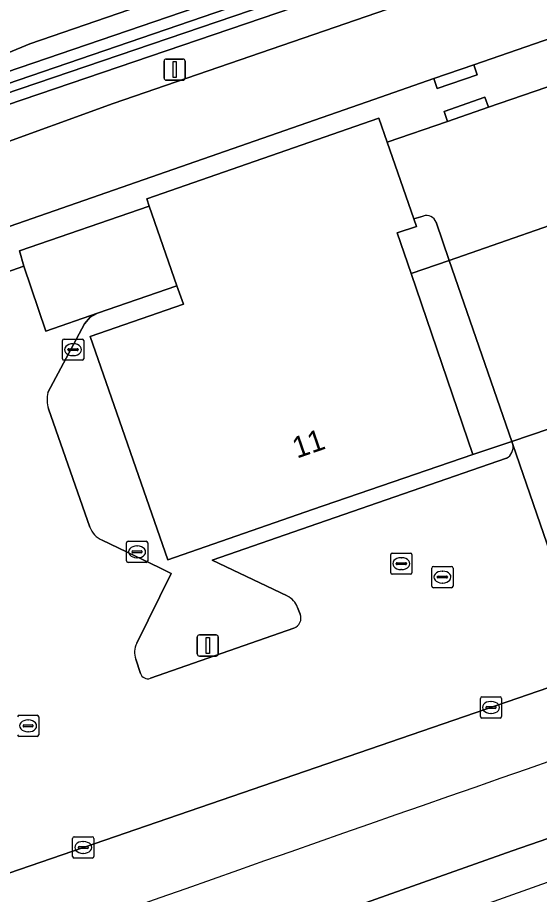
# Model space of a CAD drawing. Extents: x 162722 to 165104, y 384719 to 386284.
# Drawn here: x 164345.99 to 164370.59, y 385035.99 to 385077.31 of the extents above; entities that cross this region are included whole.
import ezdxf

# ---------------------------------------------------------------- set-up
doc = ezdxf.new("R2010")
doc.units = 0
for name, color, linetype in [('IMGEO_Fietspad_gesloten', 7, 'Continuous'), ('IMGEO_Groenvoorziening', 7, 'Continuous'), ('IMGEO_Kolk', 7, 'Continuous'), ('IMGEO_Lichtmast', 7, 'Continuous'), ('IMGEO_Loofbos', 7, 'Continuous'), ('IMGEO_Oever', 7, 'Continuous'), ('IMGEO_Pand', 7, 'Continuous'), ('IMGEO_Pand_nummerreeks', 7, 'Continuous'), ('IMGEO_Rijbaan_lokaal_gesloten', 7, 'Continuous'), ('IMGEO_Rijbaan_lokaal_open', 7, 'Continuous'), ('IMGEO_Rijbaan_regionaal_gesloten', 7, 'Continuous'), ('IMGEO_Voetpad_open', 7, 'Continuous'), ('IMGEO_Waterloop', 7, 'Continuous')]:
    doc.layers.add(name, color=color, linetype=linetype)

msp = doc.modelspace()

# ---------------------------------------------------------------- linework, layer by layer
at = {"layer": 'IMGEO_Fietspad_gesloten'}
for points in [[(164466.181, 385089.048), (164427.545, 385091.818), (164418.054, 385092.109), (164412.215, 385091.866), (164406.354, 385091.275), (164400.57, 385090.162), (164394.908, 385088.537), (164394.768, 385088.49), (164350.497, 385073.252), (164344.679, 385071.162), (164339.92, 385069.199), (164335.356, 385066.818), (164331.022, 385064.04), (164330.205, 385063.452), (164324.126, 385058.927), (164318.998, 385054.383), (164302.831, 385039.299), (164298.74, 385035.835), (164287.625, 385027.549), (164277.433, 385021.678), (164264.35, 385015.493), (164257.963, 385012.93)], [(164327.55, 385057.035), (164334.25, 385061.89), (164338.691, 385064.518), (164343.864, 385066.861), (164362.775, 385073.454), (164365.605, 385074.433), (164367.49, 385075.085), (164373.207, 385077.063), (164384.303, 385080.902), (164395.855, 385084.899), (164397.125, 385085.361), (164401.283, 385086.604), (164405.535, 385087.47), (164409.848, 385087.953), (164416.397, 385088.485), (164423.747, 385088.458), (164461.35, 385085.769)]]:
    msp.add_lwpolyline(points, dxfattribs=at)
at = {"layer": 'IMGEO_Groenvoorziening'}
for points in [[(164318.998, 385054.383), (164324.126, 385058.927), (164330.205, 385063.452), (164331.022, 385064.04), (164335.356, 385066.818), (164339.92, 385069.199), (164344.679, 385071.162), (164350.497, 385073.252), (164394.768, 385088.49), (164394.908, 385088.537), (164400.57, 385090.162), (164406.354, 385091.275), (164412.215, 385091.866), (164418.054, 385092.109), (164427.545, 385091.818), (164466.181, 385089.048)], [(164394.261, 385089.79), (164343.975, 385072.685)], [(164338.19, 385071.882), (164343.523, 385074.069), (164369.019, 385082.793), (164369.388, 385083.93), (164346.566, 385076.077), (164337.165, 385072.178), (164331.331, 385068.992), (164325.863, 385065.214), (164323.916, 385063.651), (164304.537, 385046.531), (164287.51, 385032.763), (164285.664, 385031.439), (164282.177, 385029.02), (164268.08, 385024.03), (164269.878, 385021.502), (164272.892, 385022.978)], [(164403.278, 385056.814), (164393.631, 385053.501), (164373.041, 385046.43), (164335.102, 385033.4), (164334.393, 385033.02), (164328.747, 385028.379)]]:
    msp.add_lwpolyline(points, dxfattribs=at)
msp.add_arc((165538.698, 381680.665), 3558.615, 108.517916, 109.869036, dxfattribs=at)
at = {"layer": 'IMGEO_Kolk'}
for p, q in [((164348.104, 385061.236), (164348.104, 385062.088)), ((164348.179, 385062.162), (164349.031, 385062.162)), ((164349.105, 385062.088), (164349.105, 385061.236)), ((164348.363, 385061.656), (164348.363, 385061.668)), ((164348.406, 385061.705), (164348.804, 385061.705)), ((164348.592, 385061.942), (164348.617, 385061.942)), ((164348.847, 385061.668), (164348.847, 385061.656)), ((164348.801, 385061.619), (164348.403, 385061.619)), ((164348.615, 385061.382), (164348.59, 385061.382)), ((164349.031, 385061.162), (164348.179, 385061.162)), ((164351.122, 385051.71), (164351.122, 385052.562)), ((164351.197, 385052.636), (164352.049, 385052.636)), ((164352.123, 385052.562), (164352.123, 385051.71)), ((164351.381, 385052.13), (164351.381, 385052.142)), ((164351.424, 385052.179), (164351.822, 385052.179)), ((164351.61, 385052.416), (164351.635, 385052.416)), ((164351.865, 385052.142), (164351.865, 385052.13)), ((164351.819, 385052.093), (164351.421, 385052.093)), ((164351.633, 385051.856), (164351.608, 385051.856)), ((164363.573, 385051.154), (164363.573, 385052.006)), ((164363.648, 385052.08), (164364.5, 385052.08)), ((164364.061, 385051.86), (164364.086, 385051.86)), ((164364.574, 385052.006), (164364.574, 385051.154)), ((164352.049, 385051.636), (164351.197, 385051.636)), ((164363.832, 385051.574), (164363.832, 385051.586)), ((164364.27, 385051.537), (164363.872, 385051.537)), ((164363.875, 385051.623), (164364.273, 385051.623)), ((164364.084, 385051.3), (164364.059, 385051.3)), ((164364.316, 385051.586), (164364.316, 385051.574)), ((164365.512, 385050.521), (164365.512, 385051.373)), ((164365.587, 385051.447), (164366.439, 385051.447)), ((164366.513, 385051.373), (164366.513, 385050.521)), ((164364.5, 385051.08), (164363.648, 385051.08)), ((164365.771, 385050.941), (164365.771, 385050.953)), ((164366.209, 385050.904), (164365.811, 385050.904)), ((164365.814, 385050.99), (164366.212, 385050.99)), ((164366, 385051.227), (164366.025, 385051.227)), ((164366.255, 385050.953), (164366.255, 385050.941)), ((164366.023, 385050.667), (164365.998, 385050.667)), ((164366.439, 385050.447), (164365.587, 385050.447)), ((164367.801, 385044.378), (164367.801, 385045.23)), ((164367.876, 385045.304), (164368.728, 385045.304)), ((164368.802, 385045.23), (164368.802, 385044.378)), ((164368.06, 385044.798), (164368.06, 385044.81)), ((164368.498, 385044.761), (164368.1, 385044.761)), ((164368.103, 385044.847), (164368.501, 385044.847)), ((164368.289, 385045.084), (164368.314, 385045.084)), ((164368.544, 385044.81), (164368.544, 385044.798)), ((164346.061, 385044.438), (164346.913, 385044.438)), ((164346.987, 385044.364), (164346.987, 385043.512)), ((164368.728, 385044.304), (164367.876, 385044.304)), ((164368.312, 385044.524), (164368.287, 385044.524)), ((164346.245, 385043.932), (164346.245, 385043.944)), ((164346.683, 385043.895), (164346.285, 385043.895)), ((164346.288, 385043.981), (164346.686, 385043.981)), ((164346.474, 385044.218), (164346.499, 385044.218)), ((164346.729, 385043.944), (164346.729, 385043.932)), ((164346.497, 385043.658), (164346.472, 385043.658)), ((164346.913, 385043.438), (164346.061, 385043.438)), ((164348.583, 385037.782), (164348.583, 385038.634)), ((164348.658, 385038.708), (164349.51, 385038.708)), ((164349.071, 385038.488), (164349.096, 385038.488)), ((164349.584, 385038.634), (164349.584, 385037.782)), ((164348.842, 385038.202), (164348.842, 385038.214)), ((164349.28, 385038.165), (164348.882, 385038.165)), ((164348.885, 385038.251), (164349.283, 385038.251)), ((164349.326, 385038.214), (164349.326, 385038.202)), ((164349.51, 385037.708), (164348.658, 385037.708)), ((164349.094, 385037.928), (164349.069, 385037.928))]:
    msp.add_line(p, q, dxfattribs=at)
for points in [[(164348.104, 385061.236), (164348.104, 385062.088)], [(164348.179, 385062.162), (164349.031, 385062.162)], [(164349.105, 385062.088), (164349.105, 385061.236)], [(164349.031, 385061.162), (164348.179, 385061.162)], [(164351.122, 385051.71), (164351.122, 385052.562)], [(164351.197, 385052.636), (164352.049, 385052.636)], [(164352.123, 385052.562), (164352.123, 385051.71)], [(164363.573, 385051.154), (164363.573, 385052.006)], [(164363.648, 385052.08), (164364.5, 385052.08)], [(164364.574, 385052.006), (164364.574, 385051.154)], [(164352.049, 385051.636), (164351.197, 385051.636)], [(164365.512, 385050.521), (164365.512, 385051.373)], [(164365.587, 385051.447), (164366.439, 385051.447)], [(164366.513, 385051.373), (164366.513, 385050.521)], [(164364.5, 385051.08), (164363.648, 385051.08)], [(164366.439, 385050.447), (164365.587, 385050.447)], [(164367.801, 385044.378), (164367.801, 385045.23)], [(164367.876, 385045.304), (164368.728, 385045.304)], [(164368.802, 385045.23), (164368.802, 385044.378)], [(164346.061, 385044.438), (164346.913, 385044.438)], [(164346.987, 385044.364), (164346.987, 385043.512)], [(164368.728, 385044.304), (164367.876, 385044.304)], [(164346.913, 385043.438), (164346.061, 385043.438)], [(164348.583, 385037.782), (164348.583, 385038.634)], [(164348.658, 385038.708), (164349.51, 385038.708)], [(164349.584, 385038.634), (164349.584, 385037.782)], [(164349.51, 385037.708), (164348.658, 385037.708)]]:
    msp.add_lwpolyline(points, dxfattribs=at)
for centre, radius, start, end in [((164348.181, 385062.086), 0.0765, 91.552, 178.448), ((164348.181, 385062.086), 0.0765, 91.552, 178.448), ((164349.029, 385062.086), 0.0765, 1.552, 88.448), ((164349.029, 385062.086), 0.0765, 1.552, 88.448), ((164348.403, 385061.665), 0.0403, 85.8775, 175.7526), ((164348.4, 385061.655), 0.0366, 178.938, 274.7102), ((164348.804, 385061.662), 0.043, 264.8664, 352.4533), ((164348.808, 385061.667), 0.0386, 1.7309, 96.639), ((164348.181, 385061.238), 0.0765, 181.552, 268.448), ((164348.181, 385061.238), 0.0765, 181.552, 268.448), ((164349.029, 385061.238), 0.0765, 271.552, 358.448), ((164349.029, 385061.238), 0.0765, 271.552, 358.448), ((164351.199, 385052.56), 0.0765, 91.552, 178.448), ((164351.199, 385052.56), 0.0765, 91.552, 178.448), ((164352.047, 385052.56), 0.0765, 1.552, 88.448), ((164352.047, 385052.56), 0.0765, 1.552, 88.448), ((164351.421, 385052.139), 0.0403, 85.8775, 175.7526), ((164351.418, 385052.129), 0.0366, 178.938, 274.7102), ((164351.822, 385052.136), 0.043, 264.8664, 352.4533), ((164351.826, 385052.141), 0.0386, 1.7309, 96.639), ((164351.199, 385051.712), 0.0765, 181.552, 268.448), ((164351.199, 385051.712), 0.0765, 181.552, 268.448), ((164352.047, 385051.712), 0.0765, 271.552, 358.448), ((164352.047, 385051.712), 0.0765, 271.552, 358.448), ((164363.65, 385052.004), 0.0765, 91.552, 178.448), ((164363.65, 385052.004), 0.0765, 91.552, 178.448), ((164364.498, 385052.004), 0.0765, 1.552, 88.448), ((164364.498, 385052.004), 0.0765, 1.552, 88.448), ((164363.872, 385051.583), 0.0403, 85.8775, 175.7526), ((164363.869, 385051.573), 0.0366, 178.938, 274.7102), ((164364.273, 385051.58), 0.043, 264.8664, 352.4533), ((164364.277, 385051.585), 0.0386, 1.7309, 96.639), ((164365.589, 385051.371), 0.0765, 91.552, 178.448), ((164365.589, 385051.371), 0.0765, 91.552, 178.448), ((164366.437, 385051.371), 0.0765, 1.552, 88.448), ((164366.437, 385051.371), 0.0765, 1.552, 88.448), ((164363.65, 385051.156), 0.0765, 181.552, 268.448), ((164363.65, 385051.156), 0.0765, 181.552, 268.448), ((164364.498, 385051.156), 0.0765, 271.552, 358.448), ((164364.498, 385051.156), 0.0765, 271.552, 358.448), ((164365.811, 385050.95), 0.0403, 85.8775, 175.7526), ((164365.808, 385050.94), 0.0366, 178.938, 274.7102), ((164366.212, 385050.947), 0.043, 264.8664, 352.4533), ((164366.216, 385050.952), 0.0386, 1.7309, 96.639), ((164365.589, 385050.523), 0.0765, 181.552, 268.448), ((164365.589, 385050.523), 0.0765, 181.552, 268.448), ((164366.437, 385050.523), 0.0765, 271.552, 358.448), ((164366.437, 385050.523), 0.0765, 271.552, 358.448), ((164367.878, 385045.228), 0.0765, 91.552, 178.448), ((164367.878, 385045.228), 0.0765, 91.552, 178.448), ((164368.726, 385045.228), 0.0765, 1.552, 88.448), ((164368.726, 385045.228), 0.0765, 1.552, 88.448), ((164368.1, 385044.807), 0.0403, 85.8775, 175.7526), ((164368.097, 385044.797), 0.0366, 178.938, 274.7102), ((164368.501, 385044.804), 0.043, 264.8664, 352.4533), ((164368.505, 385044.809), 0.0386, 1.7309, 96.639), ((164346.063, 385044.362), 0.0765, 91.552, 178.448), ((164346.063, 385044.362), 0.0765, 91.552, 178.448), ((164346.911, 385044.362), 0.0765, 1.552, 88.448), ((164346.911, 385044.362), 0.0765, 1.552, 88.448), ((164367.878, 385044.38), 0.0765, 181.552, 268.448), ((164367.878, 385044.38), 0.0765, 181.552, 268.448), ((164368.726, 385044.38), 0.0765, 271.552, 358.448), ((164368.726, 385044.38), 0.0765, 271.552, 358.448), ((164346.285, 385043.941), 0.0403, 85.8775, 175.7526), ((164346.282, 385043.931), 0.0366, 178.938, 274.7102), ((164346.686, 385043.938), 0.043, 264.8664, 352.4533), ((164346.69, 385043.943), 0.0386, 1.7309, 96.639), ((164346.063, 385043.514), 0.0765, 181.552, 268.448), ((164346.063, 385043.514), 0.0765, 181.552, 268.448), ((164346.911, 385043.514), 0.0765, 271.552, 358.448), ((164346.911, 385043.514), 0.0765, 271.552, 358.448), ((164348.66, 385038.632), 0.0765, 91.552, 178.448), ((164348.66, 385038.632), 0.0765, 91.552, 178.448), ((164349.508, 385038.632), 0.0765, 1.552, 88.448), ((164349.508, 385038.632), 0.0765, 1.552, 88.448), ((164348.882, 385038.211), 0.0403, 85.8775, 175.7526), ((164348.879, 385038.201), 0.0366, 178.938, 274.7102), ((164349.283, 385038.208), 0.043, 264.8664, 352.4533), ((164349.287, 385038.213), 0.0386, 1.7309, 96.639), ((164348.66, 385037.784), 0.0765, 181.552, 268.448), ((164348.66, 385037.784), 0.0765, 181.552, 268.448), ((164349.508, 385037.784), 0.0765, 271.552, 358.448), ((164349.508, 385037.784), 0.0765, 271.552, 358.448)]:
    msp.add_arc(centre, radius, start, end, dxfattribs=at)
for centre, major_axis, ratio, start_param, end_param in [((164348.591, 385061.662), (-0.387, 0.002), 0.722429, 4.712389, 7.853982), ((164348.616, 385061.662), (-0.39, 0.002), 0.717154, 1.570796, 4.712389), ((164351.609, 385052.136), (-0.387, 0.002), 0.722429, 4.712389, 7.853982), ((164351.634, 385052.136), (-0.39, 0.002), 0.717154, 1.570796, 4.712389), ((164364.06, 385051.58), (-0.387, 0.002), 0.722429, 4.712389, 7.853982), ((164364.085, 385051.58), (-0.39, 0.002), 0.717154, 1.570796, 4.712389), ((164365.999, 385050.947), (-0.387, 0.002), 0.722429, 4.712389, 7.853982), ((164366.024, 385050.947), (-0.39, 0.002), 0.717154, 1.570796, 4.712389), ((164368.288, 385044.804), (-0.387, 0.002), 0.722429, 4.712389, 7.853982), ((164368.313, 385044.804), (-0.39, 0.002), 0.717154, 1.570796, 4.712389), ((164346.473, 385043.938), (-0.387, 0.002), 0.722429, 4.712389, 7.853982), ((164346.498, 385043.938), (-0.39, 0.002), 0.717154, 1.570796, 4.712389), ((164349.07, 385038.208), (-0.387, 0.002), 0.722429, 4.712389, 7.853982), ((164349.095, 385038.208), (-0.39, 0.002), 0.717154, 1.570796, 4.712389)]:
    msp.add_ellipse(centre, major_axis=major_axis, ratio=ratio, start_param=start_param, end_param=end_param, dxfattribs=at)
at = {"layer": 'IMGEO_Lichtmast'}
for p, q in [((164352.996, 385075.356), (164353.786, 385075.356)), ((164353.786, 385075.356), (164352.996, 385075.356)), ((164352.896, 385074.456), (164352.896, 385075.256)), ((164352.896, 385075.256), (164352.896, 385074.456)), ((164353.886, 385075.256), (164353.886, 385074.456)), ((164353.886, 385074.456), (164353.886, 385075.256)), ((164353.786, 385074.356), (164352.996, 385074.356)), ((164352.996, 385074.356), (164353.786, 385074.356)), ((164354.458, 385047.325), (164354.458, 385048.125)), ((164354.458, 385048.125), (164354.458, 385047.325)), ((164354.558, 385048.225), (164355.348, 385048.225)), ((164355.348, 385048.225), (164354.558, 385048.225)), ((164355.448, 385048.125), (164355.448, 385047.325)), ((164355.448, 385047.325), (164355.448, 385048.125)), ((164355.348, 385047.225), (164354.558, 385047.225)), ((164354.558, 385047.225), (164355.348, 385047.225))]:
    msp.add_line(p, q, dxfattribs=at)
for points in [[(164353.316, 385075.231), (164353.466, 385075.231), (164353.466, 385074.481), (164353.316, 385074.481), (164353.316, 385075.231)], [(164354.878, 385048.1), (164355.028, 385048.1), (164355.028, 385047.35), (164354.878, 385047.35), (164354.878, 385048.1)]]:
    msp.add_lwpolyline(points, dxfattribs=at)
for centre, start, end in [((164352.996, 385075.256), 90, 180), ((164352.996, 385075.256), 90, 180), ((164353.786, 385075.256), 0, 90), ((164353.786, 385075.256), 360, 90), ((164352.996, 385074.456), 180, 270), ((164352.996, 385074.456), 180, 270), ((164353.786, 385074.456), 270, 0), ((164353.786, 385074.456), 270, 0), ((164354.558, 385048.125), 90, 180), ((164354.558, 385048.125), 90, 180), ((164355.348, 385048.125), 0, 90), ((164355.348, 385048.125), 360, 90), ((164354.558, 385047.325), 180, 270), ((164354.558, 385047.325), 180, 270), ((164355.348, 385047.325), 270, 0), ((164355.348, 385047.325), 270, 0)]:
    msp.add_arc(centre, 0.1, start, end, dxfattribs=at)
at = {"layer": 'IMGEO_Loofbos'}
msp.add_lwpolyline([(164323.916, 385063.651), (164325.863, 385065.214), (164331.331, 385068.992), (164337.165, 385072.178), (164346.566, 385076.077), (164369.388, 385083.93), (164370.132, 385086.222), (164354.56, 385083.887), (164342.433, 385082.528), (164311.293, 385079.851), (164305.339, 385078.79), (164303.964, 385078.112), (164304.036, 385077.108), (164304.185, 385074.376), (164240.8, 385051.931), (164241.35, 385051.172), (164248.33, 385041.532), (164255.248, 385033.867), (164265.342, 385027.017), (164268.08, 385024.03), (164282.177, 385029.02), (164285.664, 385031.439), (164287.51, 385032.763), (164304.537, 385046.531)], close=True, dxfattribs=at)
at = {"layer": 'IMGEO_Oever'}
for points in [[(164343.706, 385073.581), (164369.188, 385082.3), (164383.961, 385087.354), (164386.52, 385088.309), (164389.158, 385089.121), (164395.04, 385091.144), (164401.37, 385092.632), (164407.636, 385093.811), (164413.442, 385094.456), (164419.281, 385094.734), (164425.127, 385094.644), (164435.141, 385093.917), (164435.786, 385095.13), (164441.042, 385105.013)], [(164450.162, 385092.196), (164450.045, 385092.195), (164426.184, 385093.996), (164419.117, 385093.995), (164412.049, 385093.792), (164405.988, 385093.041), (164400, 385091.871), (164394.109, 385090.289), (164343.785, 385073.171)], [(164343.975, 385072.685), (164394.261, 385089.79)], [(164388.999, 385089.374), (164386.525, 385088.649), (164383.803, 385087.851), (164369.019, 385082.793), (164343.523, 385074.069), (164338.19, 385071.882)]]:
    msp.add_lwpolyline(points, dxfattribs=at)
at = {"layer": 'IMGEO_Pand'}
msp.add_lwpolyline([(164352.193, 385068.424), (164353.499, 385064.675), (164353.801, 385063.807), (164349.408, 385062.278), (164353.069, 385051.759), (164359.895, 385054.135), (164367.443, 385056.72), (164364.534, 385065.243), (164363.879, 385067.161), (164364.784, 385067.457), (164364.658, 385067.822), (164363.407, 385071.433), (164363.012, 385072.572), (164352.074, 385068.765)], close=True, dxfattribs=at)
at = {"layer": 'IMGEO_Rijbaan_lokaal_gesloten'}
msp.add_lwpolyline([(164352.193, 385068.424), (164346.073, 385066.315), (164346.281, 385065.59), (164347.323, 385062.535), (164349.748, 385063.375), (164353.499, 385064.675)], close=True, dxfattribs=at)
at = {"layer": 'IMGEO_Rijbaan_lokaal_open'}
for points in [[(164383.251, 385078.285), (164391.309, 385054.779), (164379.431, 385050.809), (164376.368, 385059.738), (164369.277, 385057.34), (164369.328, 385057.191), (164373.041, 385046.43), (164393.631, 385053.501), (164384.99, 385078.885)], [(164371.442, 385074.207), (164373.439, 385068.349), (164366.333, 385065.87), (164369.277, 385057.34), (164376.368, 385059.738), (164379.431, 385050.809), (164391.309, 385054.779), (164383.251, 385078.285), (164373.899, 385075.056)]]:
    msp.add_lwpolyline(points, close=True, dxfattribs=at)
for points in [[(164365.715, 385067.661), (164366.333, 385065.87), (164373.439, 385068.349), (164371.442, 385074.207), (164368.18, 385073.081), (164366.252, 385072.415), (164363.407, 385071.433), (164364.658, 385067.822), (164365.101, 385067.952)], [(164349.748, 385063.375), (164347.323, 385062.535), (164346.281, 385065.59), (164339.186, 385063.094), (164337.327, 385062.332), (164335.503, 385061.094), (164336.967, 385056.804), (164341.649, 385043.081)], [(164347.42, 385059.64), (164349.148, 385062.877), (164349.414, 385063.199), (164349.748, 385063.375)], [(164349.392, 385053.3), (164347.44, 385058.877)], [(164328.747, 385028.379), (164334.393, 385033.02), (164335.102, 385033.4), (164373.041, 385046.43), (164369.328, 385057.191)], [(164369.032, 385056.548), (164360.136, 385053.471), (164355.163, 385051.743), (164358.687, 385050.058)], [(164351.607, 385047.831), (164353.23, 385051.122), (164352.667, 385051.393), (164349.974, 385052.688)], [(164359.189, 385049.515), (164359.312, 385049.195)], [(164359.01, 385048.544), (164352.247, 385046.177)], [(164351.776, 385046.408), (164351.555, 385047.072)]]:
    msp.add_lwpolyline(points, dxfattribs=at)
for centre, radius, start, end in [((164365.265, 385067.504), 0.477, 19.2045, 110.079), ((164348.779, 385059.294), 1.402, 165.7105, 197.2926), ((164368.761, 385057.062), 0.581, 297.7852, 12.7776), ((164350.421, 385053.696), 1.103, 201.0417, 246.0797), ((164358.258, 385049.158), 0.997, 20.9817, 64.5246), ((164358.845, 385049.016), 0.5, 289.222, 21.0046), ((164352.503, 385047.388), 1, 153.7151, 198.4463), ((164352.124, 385046.522), 0.366, 198.1436, 289.6055)]:
    msp.add_arc(centre, radius, start, end, dxfattribs=at)
at = {"layer": 'IMGEO_Rijbaan_regionaal_gesloten'}
msp.add_lwpolyline([(164329.227, 385027.443), (164316.75, 385022.567), (164262.419, 385001.307), (164263.334, 384998.39), (164264.319, 384998.783), (164282.069, 385005.858), (164297.072, 385011.607), (164309.264, 385016.25), (164323.856, 385021.714), (164334.911, 385025.82), (164348.776, 385030.779), (164369.306, 385038.043), (164384.53, 385043.318), (164407.271, 385050.93), (164422.969, 385056.11), (164438.067, 385060.942), (164457.586, 385066.975), (164476.979, 385072.818), (164492.645, 385077.429), (164511.564, 385082.862), (164541.949, 385091.263), (164567.783, 385098.14)], dxfattribs=at)
msp.add_lwpolyline([(164264.016, 384996.217), (164310.692, 385015.116), (164396.361, 385045.624), (164493.508, 385076.177), (164568.271, 385096.092), (164567.783, 385098.14), (164541.949, 385091.263), (164511.564, 385082.862), (164492.645, 385077.429), (164476.979, 385072.818), (164457.586, 385066.975), (164438.067, 385060.942), (164422.969, 385056.11), (164407.271, 385050.93), (164384.53, 385043.318), (164369.306, 385038.043), (164348.776, 385030.779), (164334.911, 385025.82), (164323.856, 385021.714), (164309.264, 385016.25), (164297.072, 385011.607), (164282.069, 385005.858), (164264.319, 384998.783), (164263.334, 384998.39)], close=True, dxfattribs=at)
msp.add_arc((165538.698, 381680.665), 3558.615, 108.517916, 109.869036, dxfattribs=at)
at = {"layer": 'IMGEO_Voetpad_open'}
for points in [[(164373.207, 385077.063), (164367.49, 385075.085), (164367.653, 385074.613), (164365.768, 385073.961), (164365.605, 385074.433), (164362.775, 385073.454), (164343.864, 385066.861), (164338.691, 385064.518), (164334.25, 385061.89), (164335.411, 385058.484), (164334.035, 385058.027), (164334.419, 385056.756), (164335.898, 385057.264), (164340.501, 385044.117), (164336.107, 385042.733), (164335.774, 385042.628), (164336.068, 385041.788), (164330.095, 385039.699), (164329.33, 385041.939), (164325.923, 385040.776)], [(164341.649, 385043.081), (164336.967, 385056.804), (164335.503, 385061.094), (164337.327, 385062.332), (164339.186, 385063.094), (164346.281, 385065.59), (164346.073, 385066.315), (164352.193, 385068.424), (164352.074, 385068.765), (164363.012, 385072.572), (164363.407, 385071.433), (164366.252, 385072.415), (164366.089, 385072.887), (164368.017, 385073.553), (164368.18, 385073.081), (164371.442, 385074.207)], [(164365.101, 385067.952), (164364.658, 385067.822), (164364.784, 385067.457), (164363.879, 385067.161), (164364.534, 385065.243), (164366.333, 385065.87), (164365.715, 385067.661)], [(164353.499, 385064.675), (164349.748, 385063.375), (164349.414, 385063.199), (164349.148, 385062.877), (164347.42, 385059.64)], [(164369.328, 385057.191), (164369.277, 385057.34), (164367.443, 385056.72), (164359.895, 385054.135), (164353.069, 385051.759), (164349.408, 385062.278), (164353.801, 385063.807), (164353.499, 385064.675)], [(164347.44, 385058.877), (164349.392, 385053.3)], [(164358.687, 385050.058), (164355.163, 385051.743), (164360.136, 385053.471), (164369.032, 385056.548)], [(164349.974, 385052.688), (164352.667, 385051.393), (164353.23, 385051.122), (164351.607, 385047.831)], [(164359.312, 385049.195), (164359.189, 385049.515)], [(164352.247, 385046.177), (164359.01, 385048.544)], [(164351.555, 385047.072), (164351.776, 385046.408)]]:
    msp.add_lwpolyline(points, dxfattribs=at)
for points in [[(164365.605, 385074.433), (164365.768, 385073.961), (164367.653, 385074.613), (164367.49, 385075.085)], [(164366.252, 385072.415), (164368.18, 385073.081), (164368.017, 385073.553), (164366.089, 385072.887)], [(164366.333, 385065.87), (164364.534, 385065.243), (164367.443, 385056.72), (164369.277, 385057.34)]]:
    msp.add_lwpolyline(points, close=True, dxfattribs=at)
for centre, radius, start, end in [((164365.265, 385067.504), 0.477, 19.2045, 110.079), ((164348.779, 385059.294), 1.402, 165.7105, 197.2926), ((164368.761, 385057.062), 0.581, 297.7852, 12.7776), ((164350.421, 385053.696), 1.103, 201.0417, 246.0797), ((164358.258, 385049.158), 0.997, 20.9817, 64.5246), ((164358.845, 385049.016), 0.5, 289.222, 21.0046), ((164352.503, 385047.388), 1, 153.7151, 198.4463), ((164352.124, 385046.522), 0.366, 198.1436, 289.6055)]:
    msp.add_arc(centre, radius, start, end, dxfattribs=at)
at = {"layer": 'IMGEO_Waterloop'}
for points in [[(164441.042, 385105.013), (164435.786, 385095.13), (164435.141, 385093.917), (164425.127, 385094.644), (164419.281, 385094.734), (164413.442, 385094.456), (164407.636, 385093.811), (164401.37, 385092.632), (164395.04, 385091.144), (164389.158, 385089.121), (164386.52, 385088.309), (164383.961, 385087.354), (164369.188, 385082.3), (164343.706, 385073.581)], [(164343.785, 385073.171), (164394.109, 385090.289), (164400, 385091.871), (164405.988, 385093.041), (164412.049, 385093.792), (164419.117, 385093.995), (164426.184, 385093.996), (164450.045, 385092.195), (164450.162, 385092.196)]]:
    msp.add_lwpolyline(points, dxfattribs=at)

# ---------------------------------------------------------------- texts
at = {"layer": 'IMGEO_Pand_nummerreeks'}
msp.add_text('11', height=1, rotation=19.0337, dxfattribs=at).set_placement((164359.153, 385056.526))

doc.saveas('drawing.dxf')
